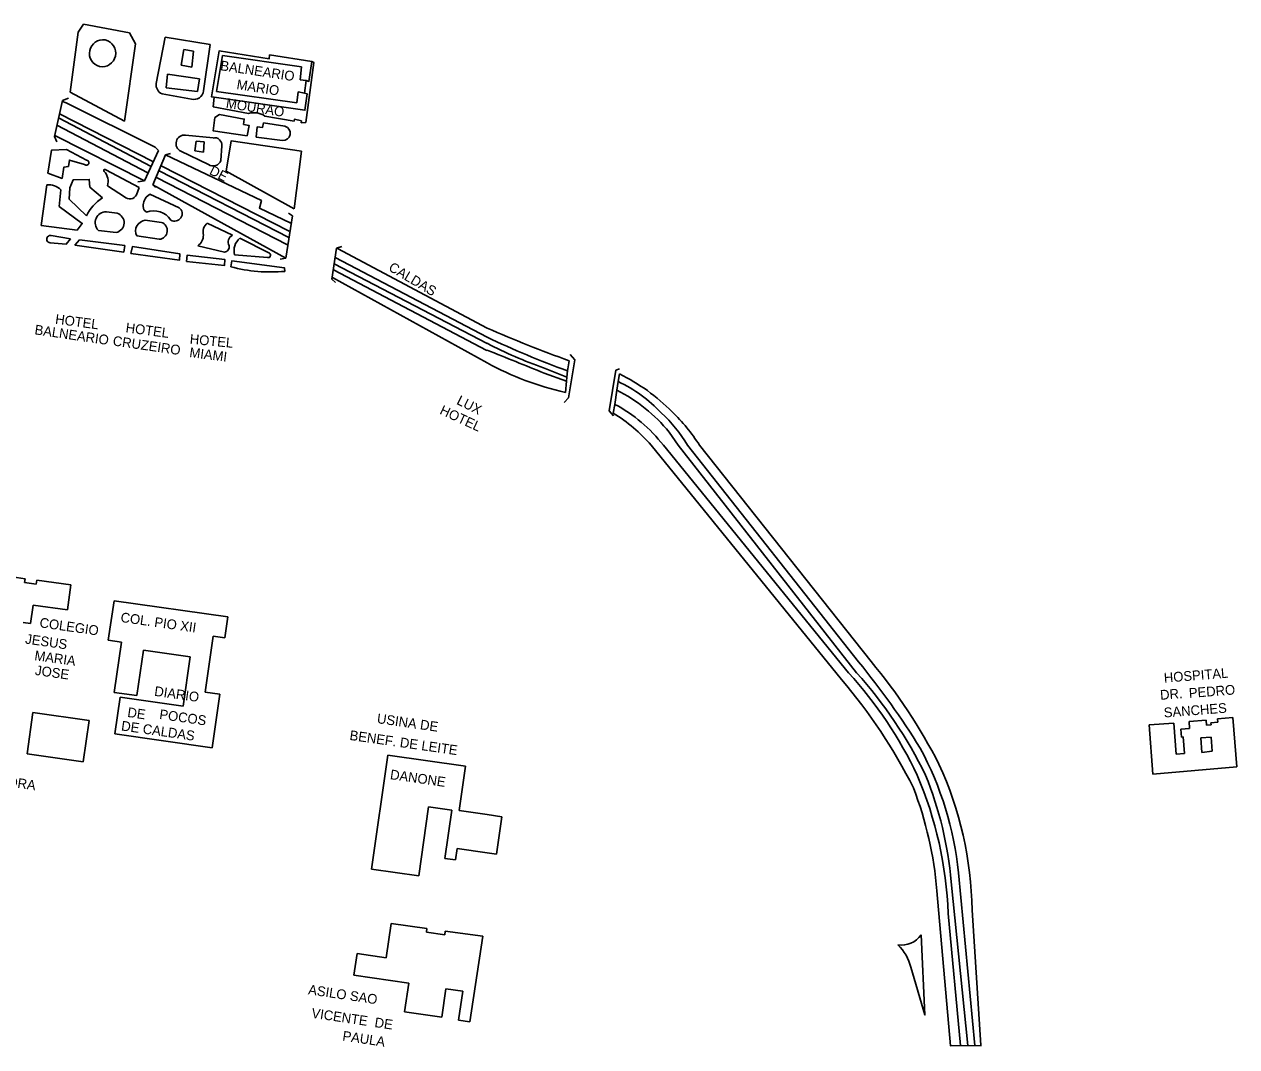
# Model space of a CAD drawing. Extents: x 325899 to 363134, y 7578590 to 7592502.
# Drawn here: x 338291.7 to 338788.7, y 7589255.2 to 7589674.6 of the extents above; entities that cross this region are included whole.
import ezdxf

# ---------------------------------------------------------------- set-up
doc = ezdxf.new("R2010")
doc.units = 0
for name, color, linetype in [('EDIFEXISTENT', 7, 'Continuous'), ('EDIFIDENTIF', 7, 'Continuous'), ('EDIFOBRAEXIS', 7, 'Continuous')]:
    doc.layers.add(name, color=color, linetype=linetype)

msp = doc.modelspace()

# ---------------------------------------------------------------- linework, layer by layer
at = {"layer": 'EDIFEXISTENT'}
for p, q in [((338356.03, 7589657.76), (338357.15, 7589664.2)), ((338357.15, 7589664.2), (338360.99, 7589663.58)), ((338360.99, 7589663.58), (338360.38, 7589656.96)), ((338360.38, 7589656.96), (338356.03, 7589657.76)), ((338370.46, 7589646.93), (338372.87, 7589661.74)), ((338372.87, 7589661.74), (338405.38, 7589657.14)), ((338405.38, 7589657.14), (338404.74, 7589651.72)), ((338349.81, 7589648.51), (338350.4, 7589654.06)), ((338350.4, 7589654.06), (338363.45, 7589652.17)), ((338363.45, 7589652.17), (338362.68, 7589647.01)), ((338362.68, 7589647.01), (338349.81, 7589648.51)), ((338404.74, 7589651.72), (338407.21, 7589651.43)), ((338407.21, 7589651.43), (338406.56, 7589646.34)), ((338304.04, 7589628.56), (338307.31, 7589643.34)), ((338307.31, 7589643.34), (338309.77, 7589644.2)), ((338403.45, 7589642.34), (338370.46, 7589646.93)), ((338403.97, 7589646.87), (338403.45, 7589642.34)), ((338406.56, 7589646.34), (338403.97, 7589646.87)), ((338304.97, 7589626.39), (338304.04, 7589628.56)), ((338346.72, 7589622.72), (338340.94, 7589610.37)), ((338345.31, 7589624.14), (338346.72, 7589622.72)), ((338361.62, 7589622.59), (338362.14, 7589626.66)), ((338365.15, 7589622.07), (338361.62, 7589622.59)), ((338362.14, 7589626.66), (338365.37, 7589626.29)), ((338365.37, 7589626.29), (338365.15, 7589622.07)), ((338344.4, 7589608.71), (338349.62, 7589621)), ((338349.62, 7589621), (338351.63, 7589621.49)), ((338340.94, 7589610.37), (338338.29, 7589609.88)), ((338345.45, 7589607.62), (338344.4, 7589608.71)), ((338401.67, 7589596.03), (338398.88, 7589578.64)), ((338399.94, 7589597.15), (338401.67, 7589596.03)), ((338417.8, 7589570.06), (338419.72, 7589582.72)), ((338419.72, 7589582.72), (338421.83, 7589583.39)), ((338398.88, 7589578.64), (338396.55, 7589578.2)), ((338419.26, 7589568.61), (338417.8, 7589570.06)), ((338515.46, 7589539.1), (338517.38, 7589536.95)), ((338517.38, 7589536.95), (338514.84, 7589521.37)), ((338531.48, 7589516.04), (338534.18, 7589532.76)), ((338534.18, 7589532.76), (338535.65, 7589533.21)), ((338514.84, 7589521.37), (338512.96, 7589519.47)), ((338533.25, 7589514.03), (338531.48, 7589516.04)), ((338281.22, 7589448.72), (338292.01, 7589447.19)), ((338292.01, 7589447.19), (338291.78, 7589445.63)), ((338291.78, 7589445.63), (338296.57, 7589444.95)), ((338296.57, 7589444.95), (338296.81, 7589446.6)), ((338296.81, 7589446.6), (338310.8, 7589444.7)), ((338310.8, 7589444.7), (338309.33, 7589434.37)), ((338295.32, 7589436.35), (338294.24, 7589428.78)), ((338309.33, 7589434.37), (338295.32, 7589436.35)), ((338326.11, 7589421.93), (338328.49, 7589438.13)), ((338328.49, 7589438.13), (338375.08, 7589431.52)), ((338294.24, 7589428.78), (338291.22, 7589429.21)), ((338375.08, 7589431.52), (338373.87, 7589422.99)), ((338369.12, 7589423.66), (338365.85, 7589400.66)), ((338373.87, 7589422.99), (338369.12, 7589423.66)), ((338331.47, 7589421.17), (338326.11, 7589421.93)), ((338328.54, 7589400.55), (338331.47, 7589421.17)), ((338340.49, 7589417.9), (338337.84, 7589399.23)), ((338359.69, 7589415.18), (338340.49, 7589417.9)), ((338356.82, 7589394.95), (338359.69, 7589415.18)), ((338337.84, 7589399.23), (338328.54, 7589400.55)), ((338328.77, 7589383.51), (338330.92, 7589398.63)), ((338330.92, 7589398.63), (338356.82, 7589394.95)), ((338365.85, 7589400.66), (338371.84, 7589399.81)), ((338371.84, 7589399.81), (338368.72, 7589377.84)), ((338292.89, 7589375.38), (338295.14, 7589392.25)), ((338295.14, 7589392.25), (338318.21, 7589388.97)), ((338318.21, 7589388.97), (338315.82, 7589372.13)), ((338769.19, 7589388.58), (338776.15, 7589389.13)), ((338769.41, 7589385.76), (338769.19, 7589388.58)), ((338776.15, 7589389.13), (338776.31, 7589387.08)), ((338780.85, 7589389.72), (338787.14, 7589390.21)), ((338780.96, 7589388.35), (338780.85, 7589389.72)), ((338787.14, 7589390.21), (338788.72, 7589370.07)), ((338752.76, 7589387.19), (338762.9, 7589387.99)), ((338754.34, 7589367.03), (338752.76, 7589387.19)), ((338762.9, 7589387.99), (338763.91, 7589375.18)), ((338765.86, 7589385.48), (338769.41, 7589385.76)), ((338766.11, 7589382.26), (338765.86, 7589385.48)), ((338776.31, 7589387.08), (338778.19, 7589387.23)), ((338778.12, 7589388.12), (338780.96, 7589388.35)), ((338778.19, 7589387.23), (338778.12, 7589388.12)), ((338368.72, 7589377.84), (338328.77, 7589383.51)), ((338766.82, 7589382.32), (338766.11, 7589382.26)), ((338767.36, 7589375.45), (338766.82, 7589382.32)), ((338773.96, 7589381.9), (338778.18, 7589382.24)), ((338774.44, 7589375.9), (338773.96, 7589381.9)), ((338778.18, 7589382.24), (338778.64, 7589376.41)), ((338315.82, 7589372.13), (338292.89, 7589375.38)), ((338434.01, 7589328.03), (338440.68, 7589374.79)), ((338440.68, 7589374.79), (338472.49, 7589370.25)), ((338763.91, 7589375.18), (338767.36, 7589375.45)), ((338778.64, 7589376.41), (338774.44, 7589375.9)), ((338472.49, 7589370.25), (338469.9, 7589352.1)), ((338788.72, 7589370.07), (338754.34, 7589367.03)), ((338457.41, 7589353.65), (338453.36, 7589325.27)), ((338466.92, 7589352.3), (338457.41, 7589353.65)), ((338464.09, 7589332.46), (338466.92, 7589352.3)), ((338469.9, 7589352.1), (338481.39, 7589350.45)), ((338481.39, 7589350.45), (338487.4, 7589349.48)), ((338487.4, 7589349.48), (338485.3, 7589334.23)), ((338469.14, 7589336.57), (338468.46, 7589331.83)), ((338481.39, 7589334.83), (338469.14, 7589336.57)), ((338485.3, 7589334.23), (338481.39, 7589334.83)), ((338468.46, 7589331.83), (338464.09, 7589332.46)), ((338453.36, 7589325.27), (338434.01, 7589328.03)), ((338440.07, 7589291.69), (338442.11, 7589305.77)), ((338442.11, 7589305.77), (338456.74, 7589303.68)), ((338456.74, 7589303.68), (338456.52, 7589302.2)), ((338456.52, 7589302.2), (338464.05, 7589301.09)), ((338464.05, 7589301.09), (338464.21, 7589302.69)), ((338464.21, 7589302.69), (338479.59, 7589300.52)), ((338479.59, 7589300.52), (338474.36, 7589265.44)), ((338426.77, 7589284.65), (338428.08, 7589293.47)), ((338428.08, 7589293.47), (338440.07, 7589291.69)), ((338449.3, 7589281.3), (338426.77, 7589284.65)), ((338447.57, 7589269.62), (338449.3, 7589281.3)), ((338464.52, 7589279), (338462.8, 7589267.36)), ((338471.46, 7589277.97), (338464.52, 7589279)), ((338469.71, 7589266.12), (338471.46, 7589277.97)), ((338462.8, 7589267.36), (338447.57, 7589269.62)), ((338474.36, 7589265.44), (338469.71, 7589266.12)), ((338684.02, 7589255.82), (338671.26, 7589255.64))]:
    msp.add_line(p, q, dxfattribs=at)
at = {"layer": 'EDIFOBRAEXIS'}
for points in [[(338310.51, 7589646.73), (338313.77, 7589671.33), (338315.98, 7589674.56), (338334.76, 7589671.06)], [(338334.76, 7589671.06), (338337.29, 7589666.47), (338332.72, 7589634.83), (338310.51, 7589646.73)], [(338345.81, 7589650.28), (338349.48, 7589669.28)], [(338349.48, 7589669.28), (338367.93, 7589666.27)], [(338367.93, 7589666.27), (338365.14, 7589647.24)], [(338383.66, 7589637.97), (338369.13, 7589640.75), (338369.5, 7589644.61), (338368.43, 7589644.76), (338371.52, 7589663.59), (338392.07, 7589660.43), (338392.14, 7589662.08)], [(338392.14, 7589662.08), (338409.52, 7589659.29)], [(338409.52, 7589659.29), (338410.37, 7589658.89), (338407.09, 7589634.32)], [(338407.21, 7589651.43), (338408.38, 7589651.08), (338409.52, 7589659.29)], [(338307.34, 7589642.81), (338308.9, 7589642.32), (338345.31, 7589624.14)], [(338360.2, 7589643.9), (338348.16, 7589646.02)], [(338369.5, 7589644.61), (338406.74, 7589639.32), (338407.61, 7589646.04), (338406.56, 7589646.34)], [(338306.13, 7589637.78), (338344.44, 7589618.24)], [(338383.05, 7589628.77), (338369.06, 7589630.88), (338369.76, 7589636.27), (338371.76, 7589637.48), (338381.84, 7589635.65), (338381.61, 7589633.49), (338383.83, 7589633.07), (338383.05, 7589628.77)], [(338305.09, 7589633.22), (338342.38, 7589613.61)], [(338305.77, 7589636.16), (338343.74, 7589616.2)], [(338386.69, 7589628.27), (338387.21, 7589632.42), (338389.35, 7589632.27), (338389.77, 7589634.11), (338398.55, 7589632.71)], [(338407.09, 7589634.32), (338405.23, 7589634.13), (338405.28, 7589634.9), (338402.45, 7589635.62), (338402.28, 7589634.86), (338390.35, 7589636.9)], [(338340.94, 7589610.37), (338304.16, 7589628.98)], [(338357.73, 7589629.12), (338369.05, 7589627.91)], [(338397.48, 7589626.91), (338386.69, 7589628.27)], [(338301.32, 7589613.44), (338302.81, 7589622.88), (338309.01, 7589623.13), (338317.24, 7589618.78)], [(338367.2, 7589617.07), (338355.82, 7589622.45)], [(338372.62, 7589624.72), (338372.26, 7589618.69)], [(338402.25, 7589598.81), (338374.43, 7589614.27), (338376.48, 7589626.69), (338405.32, 7589622.54)], [(338405.32, 7589622.54), (338402.25, 7589598.81)], [(338316.41, 7589617.08), (338310.15, 7589618.84), (338309.75, 7589616.22), (338307.84, 7589615.88), (338307.15, 7589611.35), (338301.32, 7589613.44)], [(338349.62, 7589621), (338388.89, 7589602.25), (338388.06, 7589599.19), (338400.97, 7589592.96)], [(338325.16, 7589614.79), (338338.79, 7589607.57)], [(338346.92, 7589614.41), (338400.08, 7589587.16)], [(338347.78, 7589616.52), (338400.32, 7589589.65)], [(338298.57, 7589592.02), (338300.98, 7589608.74)], [(338317.14, 7589595.98), (338310.12, 7589602.79), (338310.36, 7589607.47), (338311.65, 7589610.7), (338318.31, 7589610.91), (338318.52, 7589607.75), (338323.77, 7589603.37)], [(338332.8, 7589603.84), (338325.74, 7589608.34)], [(338338.79, 7589607.57), (338337.65, 7589604.64)], [(338344.4, 7589608.71), (338398.88, 7589578.64)], [(338345.94, 7589611.76), (338399.53, 7589584.05)], [(338306.63, 7589606.7), (338305.96, 7589599.83), (338315.45, 7589592.9), (338313.32, 7589590.17), (338298.57, 7589592.02)], [(338341.65, 7589603.59), (338343.19, 7589604.94)], [(338343.19, 7589604.94), (338355.16, 7589599.33)], [(338325.34, 7589597.68), (338329.74, 7589597.06)], [(338341.82, 7589597.51), (338340.75, 7589598.42)], [(338341.25, 7589594.2), (338347.89, 7589593.31)], [(338366.7, 7589592.99), (338376.99, 7589588.02)], [(338302.72, 7589587.95), (338310.61, 7589586.57)], [(338329.36, 7589589.15), (338322.07, 7589589.99)], [(338347.04, 7589586.37), (338337.76, 7589587.78)], [(338310.61, 7589586.57), (338308.86, 7589584.41), (338302.23, 7589584.92)], [(338312.42, 7589583.91), (338314.38, 7589586.1), (338332.84, 7589583.78), (338332.44, 7589581.13), (338312.42, 7589583.91)], [(338335.39, 7589580.61), (338336.07, 7589583.43), (338355.45, 7589580.39), (338355.26, 7589577.78), (338335.39, 7589580.61)], [(338373.76, 7589581.09), (338362.77, 7589583.72)], [(338380.07, 7589586.78), (338392.24, 7589580.62)], [(338420.05, 7589582.65), (338481.39, 7589549.93)], [(338358.19, 7589577.25), (338358.48, 7589579.87), (338373.95, 7589578.07), (338373.8, 7589575.68), (338358.19, 7589577.25)], [(338376.4, 7589575.1), (338376.79, 7589577.57), (338398.34, 7589574.67), (338398.5, 7589573.22)], [(338391.33, 7589578.86), (338377.91, 7589580.01)], [(338419.07, 7589578.93), (338481.39, 7589546.22)], [(338418.43, 7589573.85), (338481.34, 7589540.78)], [(338418.72, 7589576.31), (338481.39, 7589543.7)], [(338418.08, 7589570.72), (338481.39, 7589535.67)], [(338514.06, 7589529.81), (338504.56, 7589533.64)], [(338515.03, 7589536.55), (338514.32, 7589532.42), (338514.06, 7589529.81), (338513.91, 7589528.16), (338513.5, 7589523.58)], [(338504.86, 7589531.46), (338513.91, 7589528.16)], [(338533.15, 7589515.05), (338533.79, 7589518.67), (338534.58, 7589524.55), (338535.19, 7589528.04), (338535.67, 7589531.16)], [(338556.02, 7589507.28), (338559.67, 7589501.91)], [(338548.62, 7589501.91), (338626.71, 7589405.88)], [(338629.62, 7589408.62), (338553.69, 7589501.91)], [(338559.67, 7589501.91), (338632.89, 7589408.57)], [(338633.69, 7589413.1), (338563.62, 7589501.91)], [(338568.51, 7589501.91), (338638.81, 7589413.2)], [(338681.36, 7589255.82), (338674.64, 7589326.57)], [(338665.79, 7589319.22), (338671.42, 7589255.63)], [(338671.61, 7589322.92), (338678.47, 7589255.74)], [(338675.49, 7589255.69), (338670.42, 7589309.88)], [(338680.22, 7589311.31), (338683.86, 7589255.83), (338683.86, 7589255.83)], [(338659.32, 7589301.07), (338660.92, 7589268.3), (338655.1, 7589287.84)]]:
    msp.add_lwpolyline(points, dxfattribs=at)
for centre, radius, start, end in [((338323.95, 7589662.6), 5.57, 80.9838, 255.1417), ((338323.6, 7589662.68), 5.57, 258.8377, 77.2878), ((338349.67, 7589649.63), 3.92, 170.4485, 247.3515), ((338361.29, 7589647.61), 3.87, 253.6354, 354.5386), ((338385.89, 7589630.5), 7.8, 55.1749, 106.642), ((338397.71, 7589629.87), 2.97, 265.4447, 73.5827), ((338357.41, 7589625.6), 3.53, 84.7733, 243.2624), ((338369.84, 7589625.67), 2.37, 38.6962, 109.5102), ((338369.89, 7589625.08), 2.75, 352.5071, 48.9931), ((338317.16, 7589617.77), 1.02, 222.468, 85.4762), ((338369.14, 7589619.72), 3.28, 233.8407, 341.6812), ((338324.74, 7589614.57), 0.473, 27.7916, 235.8636), ((338320.12, 7589610.18), 5.91, 341.8635, 42.578), ((338301.66, 7589601.78), 6.99, 44.6822, 95.6153), ((338333.45, 7589588.01), 18.15, 122.214, 153.9817), ((338334.96, 7589605.84), 2.95, 222.8388, 335.9872), ((338345.67, 7589600.23), 5.24, 140.1379, 200.1376), ((338325.25, 7589593.18), 4.5, 88.8086, 224.9993), ((338344.75, 7589589.67), 8.37, 33.3043, 110.4785), ((338353.34, 7589596.87), 3.06, 238.5568, 53.5259), ((338328.51, 7589593.16), 4.09, 282.0017, 72.4962), ((338341.84, 7589589.72), 4.52, 97.5431, 205.4331), ((338346.74, 7589589.93), 3.57, 274.8968, 71.2929), ((338369.62, 7589589.35), 4.67, 128.6421, 195.414), ((338302.42, 7589586.44), 1.54, 78.429, 262.8783), ((338359.86, 7589588.1), 5.25, 303.5456, 0.0425), ((338378.34, 7589585.22), 3.11, 115.7146, 208.4185), ((338373.56, 7589583.2), 2.12, 275.378, 14.8783), ((338384.19, 7589581.73), 6.52, 129.2425, 195.3126), ((338391.58, 7589579.85), 1.02, 255.9549, 49.3276), ((338392.75, 7589636.43), 63.47, 255.0683, 275.1926), ((338714.55, 7590086.9), 585.4, 246.52925, 250.07296), ((338650.48, 7589903.4), 395.19, 244.6678, 249.8454), ((338564.21, 7589702.7), 179.27, 242.4875, 250.5675), ((345312.92, 7606444.85), 18232.18, 247.994464, 248.074002), ((338540.98, 7589645.21), 124.7, 241.4547, 257.268), ((338508.53, 7589473.09), 61.08, 43.5684, 64.1231), ((338500.09, 7589458.95), 80.5, 44.7645, 63.7681), ((338504.23, 7589464.91), 66.92, 39.2842, 63.029), ((338504.21, 7589463.35), 62.73, 37.9331, 61.8701), ((338498.49, 7589458.54), 66.29, 40.862, 58.4722), ((338513.38, 7589471.96), 58.49, 30.8034, 47.6465), ((338501.36, 7589458.29), 80.07, 33.0112, 45.7416), ((338500.68, 7589291.94), 173.9, 25.42, 42.142), ((338498.45, 7589287.63), 180.83, 25.8892, 41.9748), ((338367.52, 7589196.38), 343.24, 31.8919, 39.1527), ((338464.75, 7589267.68), 226.87, 27.1382, 39.8975), ((338452.49, 7589258.39), 228.27, 26.8227, 40.2503), ((338538.88, 7589312.9), 136.45, 5.7489, 28.3637), ((338531.96, 7589309.16), 148.27, 0.8278, 24.7202), ((338510.33, 7589303.84), 160.2, 2.1628, 23.0577), ((338524.78, 7589310.78), 147.33, 4.7262, 22.257), ((338511.7, 7589306.36), 154.62, 4.772, 20.8495), ((338651.26, 7589306.79), 9.88, 261.7622, 324.6462), ((338637.09, 7589283.62), 18.49, 13.1961, 46.4129)]:
    msp.add_arc(centre, radius, start, end, dxfattribs=at)

# ---------------------------------------------------------------- texts
at = {"layer": 'EDIFIDENTIF'}
for s, rotation, p in [('BALNEARIO', 351.4693, (338371.86, 7589655.74)), ('MARIO', 350.9912, (338378.52, 7589648.02)), ('MOURAO', 350.9912, (338374.15, 7589640.32)), ('DE', 333.0411, (338367.22, 7589613.23)), ('CALDAS', 329.3998, (338440.67, 7589573.8)), ('HOTEL', 352.4822, (338304.19, 7589551.75)), ('BALNEARIO', 351.7104, (338295.72, 7589547.43)), ('HOTEL', 352.4319, (338333.07, 7589548.25)), ('CRUZEIRO', 351.8355, (338327.77, 7589542.85)), ('HOTEL', 354.6073, (338359.39, 7589543.53)), ('MIAMI', 352.7807, (338359.21, 7589538.1)), ('HOTEL', 335.0779, (338461.67, 7589514.9)), ('LUX', 333.4612, (338468.6, 7589518.95)), ('COL. PIO XII', 351.9195, (338330.96, 7589429.47)), ('COLEGIO', 351.9195, (338297.75, 7589427.29)), ('JESUS', 351.9195, (338291.9, 7589420.62)), ('MARIA', 351.9195, (338295.67, 7589413.79)), ('JOSE', 351.9195, (338295.92, 7589407.76)), ('HOSPITAL', 4.4923, (338758.99, 7589404.54)), ('PEDRO', 4.4923, (338769.24, 7589398.26)), ('DIARIO', 351.9195, (338344.8, 7589399.19)), ('DR.', 4.4923, (338757.45, 7589397.5)), ('DE', 351.9195, (338333.77, 7589390.52)), ('POCOS', 351.9195, (338346.87, 7589389.69)), ('SANCHES', 4.4923, (338758.97, 7589390.24)), ('DE CALDAS', 351.9195, (338331.22, 7589384.98)), ('USINA DE', 351.8869, (338436.07, 7589387.98)), ('BENEF. DE LEITE', 351.8869, (338424.85, 7589381.1)), ('DANONE', 351.8869, (338441.45, 7589365.01)), ('QUADRA', 351.9195, (338273.41, 7589363.62)), ('ASILO SAO', 351.5585, (338407.89, 7589276.8)), ('VICENTE  DE', 351.5585, (338409.21, 7589267.19)), ('PAULA', 351.5585, (338421.93, 7589257.81))]:
    msp.add_text(s, height=4, rotation=rotation, dxfattribs=at).set_placement(p)

doc.saveas('drawing.dxf')
